(* Logix 5000 project; controller J1939RouterExample vendor 1 type 14 code 54 rev 19.11; software revision 19.01 *)

TASK MainTask (continuous, watchdog 500 ms) : MainProgram

MODULES
   Local : vendor 1 type 14 code 54 (ICP 0, rev 19.11)
END_MODULES

PROGRAM MainProgram   (* main routine MainRoutine *)

ROUTINE MainRoutine   (* ladder *)
END_ROUTINE
END_PROGRAM
